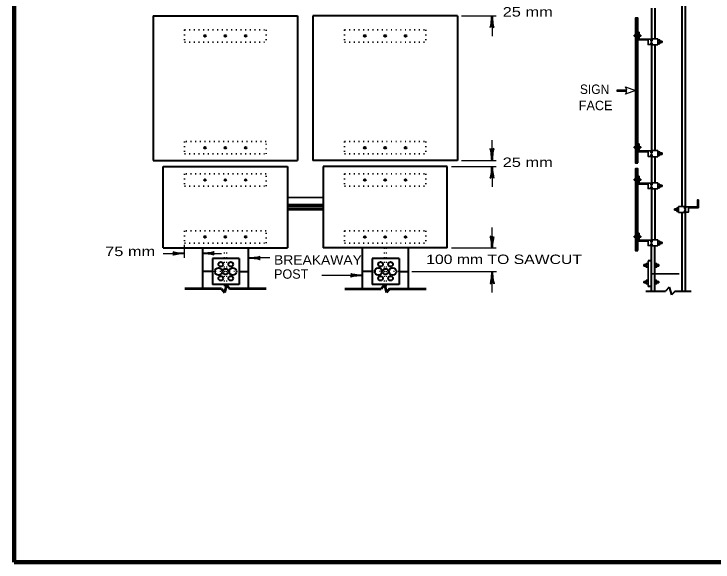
# Model space of a CAD drawing. Extents: x 851 to 1706, y -23 to 521.
# Drawn here: x 908 to 1133.3, y -11.8 to 164.8 of the extents above; entities that cross this region are included whole.
import ezdxf
from ezdxf.enums import TextEntityAlignment as Align

# ---------------------------------------------------------------- set-up
doc = ezdxf.new("R2010")
doc.units = 0
doc.header["$PDMODE"] = 32
doc.header["$PDSIZE"] = 0.5
doc.linetypes.add('DOTTED', pattern=[1.5, 0.3, -1.2])
doc.layers.add('1', color=7, linetype='Continuous', lineweight=35)

msp = doc.modelspace()

# ---------------------------------------------------------------- hatches: boundary and pattern name
at = {"layer": '1'}
for points in [[(969.881, 157.69, 1), (969.309, 157.69, 1)], [(976.442, 157.69, 1), (975.87, 157.69, 1)], [(983.003, 157.69, 1), (982.431, 157.69, 1)], [(1021.412, 157.69, 1), (1020.841, 157.69, 1)], [(1027.973, 157.69, 1), (1027.402, 157.69, 1)], [(1034.534, 157.69, 1), (1033.963, 157.69, 1)], [(969.881, 121.659, 1), (969.309, 121.659, 1)], [(976.442, 121.659, 1), (975.87, 121.659, 1)], [(983.003, 121.659, 1), (982.431, 121.659, 1)], [(1021.412, 121.659, 1), (1020.841, 121.659, 1)], [(1027.973, 121.659, 1), (1027.402, 121.659, 1)], [(1034.534, 121.659, 1), (1033.963, 121.659, 1)], [(969.881, 111.271, 1), (969.309, 111.271, 1)], [(976.442, 111.271, 1), (975.87, 111.271, 1)], [(983.003, 111.271, 1), (982.431, 111.271, 1)], [(1021.412, 111.271, 1), (1020.841, 111.271, 1)], [(1027.973, 111.271, 1), (1027.402, 111.271, 1)], [(1034.534, 111.271, 1), (1033.963, 111.271, 1)], [(969.881, 92.914, 1), (969.309, 92.914, 1)], [(976.442, 92.914, 1), (975.87, 92.914, 1)], [(983.003, 92.914, 1), (982.431, 92.914, 1)], [(1021.412, 92.9, 1), (1020.841, 92.9, 1)], [(1027.973, 92.9, 1), (1027.402, 92.9, 1)], [(1034.534, 92.9, 1), (1033.963, 92.9, 1)]]:
    msp.add_hatch(color=256, dxfattribs=at).paths.add_polyline_path(points)

# ---------------------------------------------------------------- linework, layer by layer
at = {"layer": '1', "lineweight": 40}
for p, q in [((1124.325, 182.416), (1124.325, 75.472)), ((1123.292, 172.875), (1123.292, 102.727)), ((1113.5, 166.697), (1113.5, 156.773)), ((1114.533, 166.697), (1114.533, 156.773)), ((952.865, 164.169), (999.448, 164.169)), ((952.865, 164.169), (952.865, 117.586)), ((999.448, 164.169), (999.448, 117.586)), ((1050.979, 164.169), (1004.396, 164.169)), ((1004.396, 164.169), (1004.396, 117.586)), ((1050.979, 164.169), (1050.979, 117.586)), ((1113.5, 154.805), (1113.5, 120.743)), ((1114.533, 154.805), (1114.533, 120.743)), ((952.865, 117.586), (999.448, 117.586)), ((1050.979, 117.586), (1004.396, 117.586)), ((1113.5, 118.774), (1113.5, 110.354)), ((1114.533, 118.774), (1114.533, 110.354)), ((956.145, 89.374), (956.145, 115.618)), ((956.145, 115.618), (996.167, 115.618)), ((956.145, 89.374), (956.145, 115.618)), ((996.167, 115.618), (996.167, 89.374)), ((996.167, 115.618), (996.167, 89.374)), ((1007.676, 115.618), (1007.676, 89.374)), ((1007.676, 115.618), (1007.676, 89.374)), ((1047.698, 115.618), (1007.676, 115.618)), ((1007.676, 115.618), (1007.676, 89.374)), ((1047.698, 89.374), (1047.698, 115.618)), ((1047.698, 89.374), (1047.698, 115.618)), ((1113.5, 108.386), (1113.5, 91.984)), ((1114.533, 108.386), (1114.533, 91.984)), ((1123.292, 100.759), (1123.292, 75.472)), ((956.145, 89.374), (996.167, 89.374)), ((956.145, 89.374), (996.167, 89.374)), ((968.775, 89.374), (968.775, 76.252)), ((983.537, 89.374), (983.537, 76.252)), ((1047.698, 89.374), (1007.676, 89.374)), ((1047.698, 89.374), (1007.676, 89.374)), ((1020.306, 89.374), (1020.306, 76.252)), ((1035.068, 89.374), (1035.068, 76.252)), ((1113.5, 75.472), (1113.5, 90.015)), ((1114.533, 75.472), (1114.533, 90.015)), ((980.667, 85.984), (972.028, 85.984)), ((972.028, 85.984), (972.028, 77.619)), ((980.667, 85.984), (980.667, 77.619)), ((1032.17, 85.984), (1023.532, 85.984)), ((1023.532, 85.984), (1023.532, 77.619)), ((1032.17, 85.984), (1032.17, 77.619)), ((1113.5, 85.258), (1112.417, 85.258)), ((972.028, 81.774), (968.83, 81.774)), ((980.667, 81.774), (983.592, 81.774)), ((1023.532, 81.774), (1020.361, 81.774)), ((1032.17, 81.774), (1035.123, 81.774)), ((980.667, 77.619), (972.028, 77.619)), ((1032.17, 77.619), (1023.532, 77.619)), ((1113.5, 76.893), (1112.417, 76.893)), ((1119.241, 76.757), (1118.027, 75.472)), ((1119.241, 76.757), (1119.995, 74.241)), ((1111.728, 75.472), (1118.027, 75.472)), ((1121.176, 75.472), (1119.995, 74.241)), ((1121.176, 75.472), (1126.294, 75.472))]:
    msp.add_line(p, q, dxfattribs=at)
at = {"layer": '1', "lineweight": 25}
for p, q in [((1052.291, 164.169), (1063.445, 164.169)), ((1062.132, 164.169), (1062.132, 157.608)), ((1062.132, 117.586), (1062.132, 124.147)), ((1052.291, 117.586), (1063.445, 117.586)), ((1049.01, 115.618), (1063.445, 115.618)), ((1062.132, 115.618), (1062.132, 109.057)), ((1128.688, 104.859), (1128.295, 104.859)), ((1128.688, 104.859), (1128.688, 102.344)), ((1062.132, 89.347), (1062.132, 95.907)), ((962.942, 90.378), (962.942, 86.139)), ((1049.01, 89.374), (1063.445, 89.374)), ((956.107, 87.632), (962.997, 87.632)), ((968.737, 87.632), (974.916, 87.632)), ((990.454, 86.148), (983.592, 86.148)), ((1036.216, 81.774), (1063.499, 81.774)), ((1062.187, 75.049), (1062.187, 81.61)), ((1020.361, 80.544), (1007.225, 80.544))]:
    msp.add_line(p, q, dxfattribs=at)
at = {"layer": '1', "linetype": 'DOTTED'}
for p, q in [((963.034, 159.686), (989.278, 159.686)), ((963.034, 159.686), (963.034, 155.695)), ((989.278, 159.686), (989.278, 155.695)), ((1014.565, 159.686), (1040.809, 159.686)), ((1014.565, 159.686), (1014.565, 155.695)), ((1040.809, 159.686), (1040.809, 155.695)), ((963.034, 155.695), (989.278, 155.695)), ((1014.565, 155.695), (1040.809, 155.695)), ((1014.565, 123.655), (1040.809, 123.655)), ((1014.565, 123.655), (1014.565, 119.664)), ((1040.809, 123.655), (1040.809, 119.664)), ((1014.565, 119.664), (1040.809, 119.664)), ((1014.565, 113.267), (1040.809, 113.267)), ((1014.565, 113.267), (1014.565, 109.276)), ((1040.809, 113.267), (1040.809, 109.276)), ((1014.565, 109.276), (1040.809, 109.276)), ((1014.565, 94.896), (1040.809, 94.896)), ((1014.565, 94.896), (1014.565, 90.905)), ((1040.809, 94.896), (1040.809, 90.905)), ((1014.565, 90.905), (1040.809, 90.905))]:
    msp.add_line(p, q, dxfattribs=at)
at = {"layer": '1'}
for p, q in [((1107.876, 157.949), (1107.876, 157.648)), ((1109.137, 157.949), (1107.876, 157.949)), ((1109.137, 158.906), (1109.137, 156.391)), ((1109.793, 158.113), (1109.497, 158.113)), ((1110.055, 157.949), (1109.497, 157.949)), ((1109.793, 158.113), (1109.793, 157.484)), ((1110.055, 157.949), (1110.055, 157.648)), ((1109.137, 157.648), (1107.876, 157.648)), ((1110.055, 157.648), (1109.497, 157.648)), ((1109.793, 157.484), (1109.497, 157.484)), ((1113.5, 156.773), (1115.566, 156.773)), ((1113.5, 156.09), (1113.5, 156.773)), ((1113.5, 156.09), (1113.5, 155.489)), ((1113.5, 155.051), (1113.5, 155.489)), ((1115.566, 156.773), (1115.566, 154.805)), ((1115.566, 156.391), (1116.177, 156.391)), ((1115.566, 156.09), (1116.177, 156.09)), ((1115.566, 155.489), (1116.177, 155.489)), ((1116.177, 156.391), (1116.177, 155.161)), ((1116.177, 156.035), (1116.911, 156.035)), ((1116.177, 155.543), (1116.911, 155.543)), ((1116.369, 155.899), (1116.369, 155.653)), ((1116.547, 156.035), (1116.547, 155.543)), ((1116.747, 155.899), (1116.747, 155.653)), ((1116.911, 156.035), (1116.911, 155.543)), ((1113.5, 155.051), (1113.5, 154.805)), ((1113.5, 154.805), (1115.566, 154.805)), ((1115.566, 155.161), (1116.177, 155.161)), ((1107.876, 121.918), (1107.876, 121.617)), ((1109.137, 121.918), (1107.876, 121.918)), ((1109.137, 122.875), (1109.137, 120.36)), ((1109.793, 122.082), (1109.497, 122.082)), ((1110.055, 121.918), (1109.497, 121.918)), ((1109.793, 122.082), (1109.793, 121.453)), ((1110.055, 121.918), (1110.055, 121.617)), ((1109.137, 121.617), (1107.876, 121.617)), ((1110.055, 121.617), (1109.497, 121.617)), ((1109.793, 121.453), (1109.497, 121.453)), ((1113.5, 120.743), (1115.566, 120.743)), ((1113.5, 120.059), (1113.5, 120.743)), ((1113.5, 120.059), (1113.5, 119.458)), ((1113.5, 119.02), (1113.5, 119.458)), ((1115.566, 120.743), (1115.566, 118.774)), ((1115.566, 120.36), (1116.177, 120.36)), ((1115.566, 120.059), (1116.177, 120.059)), ((1115.566, 119.458), (1116.177, 119.458)), ((1116.177, 120.36), (1116.177, 119.13)), ((1116.177, 120.005), (1116.911, 120.005)), ((1116.177, 119.512), (1116.911, 119.512)), ((1116.369, 119.868), (1116.369, 119.622)), ((1116.547, 120.005), (1116.547, 119.512)), ((1116.747, 119.868), (1116.747, 119.622)), ((1116.911, 120.005), (1116.911, 119.512)), ((1113.5, 119.02), (1113.5, 118.774)), ((1113.5, 118.774), (1115.566, 118.774)), ((1115.566, 119.13), (1116.177, 119.13)), ((1107.876, 111.53), (1107.876, 111.229)), ((1109.137, 111.53), (1107.876, 111.53)), ((1109.137, 111.229), (1107.876, 111.229)), ((1109.137, 112.487), (1109.137, 109.972)), ((1109.793, 111.694), (1109.497, 111.694)), ((1110.055, 111.53), (1109.497, 111.53)), ((1110.055, 111.229), (1109.497, 111.229)), ((1109.793, 111.065), (1109.497, 111.065)), ((1109.793, 111.694), (1109.793, 111.065)), ((1110.055, 111.53), (1110.055, 111.229)), ((1113.5, 110.354), (1115.566, 110.354)), ((1113.5, 109.671), (1113.5, 110.354)), ((1113.5, 109.671), (1113.5, 109.07)), ((1113.5, 108.632), (1113.5, 109.07)), ((1113.5, 108.632), (1113.5, 108.386)), ((1113.5, 108.386), (1115.566, 108.386)), ((1115.566, 110.354), (1115.566, 108.386)), ((1115.566, 109.972), (1116.177, 109.972)), ((1115.566, 109.671), (1116.177, 109.671)), ((1115.566, 109.07), (1116.177, 109.07)), ((1115.566, 108.741), (1116.177, 108.741)), ((1116.177, 109.972), (1116.177, 108.741)), ((1116.177, 109.616), (1116.911, 109.616)), ((1116.177, 109.124), (1116.911, 109.124)), ((1116.369, 109.48), (1116.369, 109.234)), ((1116.547, 109.616), (1116.547, 109.124)), ((1116.747, 109.48), (1116.747, 109.234)), ((1116.911, 109.616), (1116.911, 109.124)), ((996.167, 105.64), (1007.676, 105.64)), ((1128.688, 104.859), (1128.688, 102.344)), ((996.167, 103.425), (1007.676, 103.425)), ((1007.676, 102.824), (996.167, 102.824)), ((1007.676, 102.195), (996.167, 102.195)), ((996.167, 101.648), (1007.676, 101.648)), ((1121.648, 101.989), (1120.913, 101.989)), ((1120.913, 101.989), (1120.913, 101.497)), ((1121.648, 101.497), (1120.913, 101.497)), ((1121.078, 101.852), (1121.078, 101.606)), ((1121.278, 101.989), (1121.278, 101.497)), ((1121.456, 101.852), (1121.456, 101.606)), ((1122.259, 102.344), (1121.648, 102.344)), ((1121.648, 102.344), (1121.648, 101.114)), ((1122.259, 102.044), (1121.648, 102.044)), ((1122.259, 101.442), (1121.648, 101.442)), ((1124.325, 102.727), (1122.259, 102.727)), ((1122.259, 102.727), (1122.259, 100.759)), ((1124.325, 102.044), (1124.325, 102.727)), ((1124.325, 102.044), (1124.325, 101.442)), ((1124.325, 101.005), (1124.325, 101.442)), ((1122.259, 101.114), (1121.648, 101.114)), ((1124.325, 100.759), (1122.259, 100.759)), ((1124.325, 101.005), (1124.325, 100.759)), ((1107.876, 93.159), (1107.876, 92.858)), ((1109.137, 93.159), (1107.876, 93.159)), ((1109.137, 92.858), (1107.876, 92.858)), ((1109.137, 94.116), (1109.137, 91.601)), ((1109.793, 93.323), (1109.497, 93.323)), ((1110.055, 93.159), (1109.497, 93.159)), ((1110.055, 92.858), (1109.497, 92.858)), ((1109.793, 92.694), (1109.497, 92.694)), ((1109.793, 93.323), (1109.793, 92.694)), ((1110.055, 93.159), (1110.055, 92.858)), ((1113.5, 91.984), (1115.566, 91.984)), ((1113.5, 91.3), (1113.5, 91.984)), ((1113.5, 91.3), (1113.5, 90.699)), ((1113.5, 90.261), (1113.5, 90.699)), ((1113.5, 90.261), (1113.5, 90.015)), ((1115.566, 91.984), (1115.566, 90.015)), ((1115.566, 91.3), (1116.177, 91.3)), ((1115.566, 90.699), (1116.177, 90.699)), ((1116.177, 91.245), (1116.911, 91.245)), ((1116.177, 90.753), (1116.911, 90.753)), ((1116.369, 91.109), (1116.369, 90.863)), ((1116.547, 91.245), (1116.547, 90.753)), ((1116.747, 91.109), (1116.747, 90.863)), ((1116.911, 91.245), (1116.911, 90.753)), ((1113.5, 90.015), (1115.566, 90.015)), ((1111.807, 84.03), (1111.066, 84.03)), ((1111.066, 84.03), (1111.066, 83.538)), ((1111.807, 83.538), (1111.066, 83.538)), ((1111.23, 83.894), (1111.23, 83.648)), ((1111.43, 84.03), (1111.43, 83.538)), ((1111.608, 83.894), (1111.608, 83.648)), ((1112.417, 84.09), (1111.807, 84.09)), ((1112.417, 83.475), (1111.807, 83.475)), ((1112.417, 85.258), (1112.417, 76.893)), ((1114.533, 84.09), (1115.144, 84.09)), ((1114.533, 83.475), (1115.144, 83.475)), ((1115.144, 84.03), (1115.884, 84.03)), ((1115.144, 83.538), (1115.884, 83.538)), ((1115.342, 83.894), (1115.342, 83.648)), ((1115.52, 84.03), (1115.52, 83.538)), ((1115.72, 83.894), (1115.72, 83.648)), ((1115.884, 84.03), (1115.884, 83.538)), ((1111.807, 83.167), (1112.417, 83.167)), ((1115.144, 83.167), (1114.533, 83.167)), ((1111.807, 78.984), (1112.417, 78.984)), ((1113.5, 81.049), (1122.384, 81.049)), ((1111.807, 78.608), (1111.071, 78.608)), ((1111.071, 78.608), (1111.071, 78.116)), ((1111.807, 78.116), (1111.071, 78.116)), ((1111.236, 78.471), (1111.236, 78.225)), ((1111.436, 78.608), (1111.436, 78.116)), ((1111.614, 78.471), (1111.614, 78.225)), ((1112.417, 78.677), (1111.807, 78.677)), ((1112.417, 78.062), (1111.807, 78.062)), ((1114.533, 78.677), (1115.144, 78.677)), ((1114.533, 78.062), (1115.144, 78.062)), ((1115.144, 78.608), (1115.879, 78.608)), ((1115.144, 78.116), (1115.879, 78.116)), ((1115.336, 78.471), (1115.336, 78.225)), ((1115.515, 78.608), (1115.515, 78.116)), ((1115.715, 78.471), (1115.715, 78.225)), ((1115.879, 78.608), (1115.879, 78.116))]:
    msp.add_line(p, q, dxfattribs=at)
at = {"layer": '1', "linetype": 'DOTTED', "lineweight": 25}
for p, q in [((1040.809, 123.655), (1040.809, 119.664)), ((1040.809, 113.267), (1040.809, 109.276)), ((1040.809, 94.896), (1040.809, 90.932)), ((1040.809, 94.896), (1040.809, 90.905)), ((975.828, 89.374), (975.828, 74.912)), ((976.484, 89.374), (976.484, 77.482)), ((1027.359, 89.374), (1027.359, 77.482)), ((1028.015, 89.374), (1028.015, 74.912)), ((980.667, 81.774), (972.028, 81.774)), ((1032.17, 81.774), (1023.532, 81.774))]:
    msp.add_line(p, q, dxfattribs=at)
at = {"layer": '1', "lineweight": 53}
for p, q in [((976.484, 77.482), (975.883, 74.967)), ((976.484, 77.482), (977.523, 76.197)), ((1027.441, 77.482), (1026.43, 76.197)), ((1027.441, 77.482), (1028.07, 74.967)), ((974.898, 76.197), (963.089, 76.197)), ((974.898, 76.197), (975.883, 74.967)), ((989.333, 76.197), (977.523, 76.197)), ((1014.62, 76.197), (1026.43, 76.197)), ((1029.054, 76.197), (1028.07, 74.967)), ((1029.054, 76.197), (1040.864, 76.197))]:
    msp.add_line(p, q, dxfattribs=at)
at = {"layer": '1', "lineweight": 158}
msp.add_line((1699.744, -11.848), (908.144, -11.848), dxfattribs=at)
msp.add_lwpolyline([(1699.744, 514.252), (908.044, 514.152), (908.144, -11.848)], dxfattribs=at)
at = {"layer": '1', "lineweight": 40}
for points in [[(1109.137, 116.806), (1109.137, 163.389), (1108.307, 163.389), (1108.307, 116.806)], [(1109.137, 88.594), (1109.137, 114.838), (1108.307, 114.838), (1108.307, 88.594)]]:
    msp.add_lwpolyline(points, close=True, dxfattribs=at)
at = {"layer": '1', "lineweight": 25}
for points in [[(1109.137, 158.906), (1109.497, 158.906), (1109.497, 156.691)], [(1109.137, 122.875), (1109.497, 122.875), (1109.497, 120.66)], [(1109.137, 112.487), (1109.497, 112.487), (1109.497, 110.272)], [(1109.137, 112.487), (1109.497, 112.487), (1109.497, 110.272)], [(1109.137, 94.116), (1109.497, 94.116), (1109.497, 91.901)]]:
    msp.add_lwpolyline(points, dxfattribs=at)
at = {"layer": '1'}
for points in [[(1109.137, 158.906), (1109.497, 158.906), (1109.497, 156.691), (1113.5, 156.691)], [(1113.5, 154.915), (1112.417, 154.915), (1112.417, 156.391), (1109.137, 156.391)], [(1109.137, 122.875), (1109.497, 122.875), (1109.497, 120.661), (1113.5, 120.661)], [(1113.5, 118.884), (1112.417, 118.884), (1112.417, 120.36), (1109.137, 120.36)], [(1109.137, 112.487), (1109.497, 112.487), (1109.497, 110.272), (1113.5, 110.272)], [(1113.5, 108.495), (1112.417, 108.495), (1112.417, 109.972), (1109.137, 109.972)], [(1128.688, 104.859), (1128.327, 104.859), (1128.327, 102.645), (1124.325, 102.645)], [(1124.325, 100.868), (1125.408, 100.868), (1125.408, 102.344), (1128.688, 102.344)], [(1109.137, 94.116), (1109.497, 94.116), (1109.497, 91.901), (1113.5, 91.901)], [(1113.5, 90.125), (1112.417, 90.125), (1112.417, 91.601), (1109.137, 91.601)], [(1115.566, 91.601), (1116.177, 91.601), (1116.177, 90.371), (1115.566, 90.371)], [(1112.417, 84.397), (1111.807, 84.397), (1111.807, 83.167), (1112.417, 83.167)], [(1114.533, 84.397), (1115.144, 84.397), (1115.144, 83.167), (1114.533, 83.167)], [(1112.417, 78.984), (1111.807, 78.984), (1111.807, 77.754), (1112.417, 77.754)], [(1114.533, 78.984), (1115.144, 78.984), (1115.144, 77.754), (1114.533, 77.754)]]:
    msp.add_lwpolyline(points, dxfattribs=at)
at = {"layer": '1', "lineweight": 25}
msp.add_lwpolyline([(1105.518, 139.797), (1102.402, 139.797), (1102.402, 140.371), (1105.518, 140.371), (1105.163, 141.273), (1108.307, 140.097), (1105.163, 138.895)], close=True, dxfattribs=at)
msp.add_lwpolyline([(1105.518, 139.797), (1102.402, 139.797), (1102.402, 140.371), (1105.518, 140.371), (1105.163, 141.273), (1108.307, 140.097), (1105.163, 138.895)], close=True, dxfattribs=at)
at = {"layer": '1', "linetype": 'DOTTED'}
for points in [[(989.278, 123.655), (963.034, 123.655), (963.034, 119.664), (989.278, 119.664)], [(989.278, 113.267), (963.034, 113.267), (963.034, 109.276), (989.278, 109.276)], [(989.278, 94.896), (963.034, 94.896), (963.034, 90.932), (989.278, 90.932)]]:
    msp.add_lwpolyline(points, close=True, dxfattribs=at)
at = {"layer": '1', "lineweight": 40}
for centre, radius in [((969.595, 157.69), 0.286), ((976.156, 157.69), 0.286), ((982.717, 157.69), 0.286), ((1021.126, 157.69), 0.286), ((1027.687, 157.69), 0.286), ((1034.248, 157.69), 0.286), ((969.595, 121.659), 0.286), ((976.156, 121.659), 0.286), ((982.717, 121.659), 0.286), ((1021.126, 121.659), 0.286), ((1027.687, 121.659), 0.286), ((1034.248, 121.659), 0.286), ((969.595, 111.271), 0.286), ((976.156, 111.271), 0.286), ((982.717, 111.271), 0.286), ((1021.126, 111.271), 0.286), ((1027.687, 111.271), 0.286), ((1034.248, 111.271), 0.286), ((969.595, 92.914), 0.286), ((976.156, 92.914), 0.286), ((982.717, 92.914), 0.286), ((1021.126, 92.9), 0.286), ((1027.687, 92.9), 0.286), ((1034.248, 92.9), 0.286), ((974.686, 84.114), 0.745), ((977.909, 84.114), 0.745), ((1026.206, 84.114), 0.745), ((1029.429, 84.114), 0.745), ((973.943, 81.792), 1.17), ((976.216, 81.764), 0.927), ((978.58, 81.792), 1.17), ((1025.463, 81.792), 1.17), ((1027.736, 81.764), 0.927), ((1030.1, 81.792), 1.17), ((974.686, 79.576), 0.745), ((977.909, 79.576), 0.745), ((1026.206, 79.576), 0.745), ((1029.429, 79.576), 0.745)]:
    msp.add_circle(centre, radius, dxfattribs=at)
for centre, major_axis, ratio, start_param, end_param in [((1061.842, 162.705), (0.23, 2.305), 0.07063, 3.1407148, 5.41811), ((1061.842, 162.705), (0.23, 2.305), 0.07063, 3.1407148, 5.41811), ((1062.482, 162.743), (-0.205, 2.343), 0.122415, 0.8963533, 3.1415927), ((1062.482, 162.743), (-0.205, 2.343), 0.122415, 0.8963533, 3.1415927), ((1061.842, 119.062), (0.23, -2.305), 0.07063, 0.8650754, 3.1424706), ((1061.842, 119.062), (0.23, -2.305), 0.07063, 0.8650754, 3.1424706), ((1062.482, 119.024), (-0.205, -2.343), 0.122415, 3.1415927, 5.386832), ((1062.482, 119.024), (-0.205, -2.343), 0.122415, 3.1415927, 5.386832), ((1061.757, 114.192), (0.205, 2.343), 0.122415, 3.1415927, 5.386832), ((1061.757, 114.192), (0.205, 2.343), 0.122415, 3.1415927, 5.386832), ((1062.398, 114.154), (-0.23, 2.305), 0.07063, 0.8650754, 3.1424706), ((1062.398, 114.154), (-0.23, 2.305), 0.07063, 0.8650754, 3.1424706), ((1061.757, 90.768), (0.205, -2.343), 0.122415, 0.8963533, 3.1415927), ((1062.398, 90.806), (-0.23, -2.305), 0.07063, 3.1407148, 5.41811), ((961.561, 87.981), (2.343, -0.205), 0.122415, 3.1415927, 5.386832), ((970.204, 87.896), (-2.305, -0.23), 0.07063, 0.8650754, 3.1424706), ((961.522, 87.341), (2.305, 0.23), 0.07063, 0.8650754, 3.1424706), ((970.165, 87.256), (-2.343, 0.205), 0.122415, 3.1415927, 5.386832), ((985.02, 86.509), (-2.343, -0.205), 0.122415, 0.8963533, 3.1415927), ((985.02, 86.509), (-2.343, -0.205), 0.122415, 0.8963533, 3.1415927), ((985.058, 85.869), (-2.305, 0.23), 0.07063, 3.1407148, 5.41811), ((985.058, 85.869), (-2.305, 0.23), 0.07063, 3.1407148, 5.41811), ((1061.897, 80.15), (0.23, 2.305), 0.07063, 3.1407148, 5.41811), ((1062.537, 80.189), (-0.205, 2.343), 0.122415, 0.8963533, 3.1415927), ((1018.916, 80.187), (2.343, 0.205), 0.122415, 0.8963533, 3.1415927), ((1018.878, 80.827), (2.305, -0.23), 0.07063, 3.1407148, 5.41811)]:
    msp.add_ellipse(centre, major_axis=major_axis, ratio=ratio, start_param=start_param, end_param=end_param, dxfattribs=at)
at = {"layer": '1'}
for p in [(1113.5, 156.281), (1113.5, 155.243), (1113.5, 120.251), (1113.5, 119.212), (1113.5, 109.862), (1113.5, 108.823), (1124.325, 102.235), (1124.325, 101.196), (1113.5, 91.491), (1113.5, 90.453)]:
    msp.add_point(p, dxfattribs=at)

# ---------------------------------------------------------------- texts
for s, width, p in [('25 mm', 1.3, (1073.615, 163.944)), ('SIGN', 0.95, (1095.149, 139)), ('25 mm', 1.3, (1073.615, 115.476)), ('75 mm', 1.3, (945.497, 86.755)), ('100 mm TO SAWCUT', 1.25, (1065.994, 84.192))]:
    msp.add_text(s, height=3.037, dxfattribs=dict(at, width=width)).set_placement(p, align=Align.CENTER)
msp.add_text('FACE', height=3.037, dxfattribs=at).set_placement((1095.485, 133.767), align=Align.CENTER)
at = {"layer": '1', "width": 1.1}
msp.add_text('BREAKAWAY ', height=3.037, dxfattribs=at).set_placement((991.855, 84.005))
at = {"layer": '1'}
msp.add_text('POST', height=3.037, dxfattribs=at).set_placement((991.855, 79.449))

doc.saveas('drawing.dxf')
